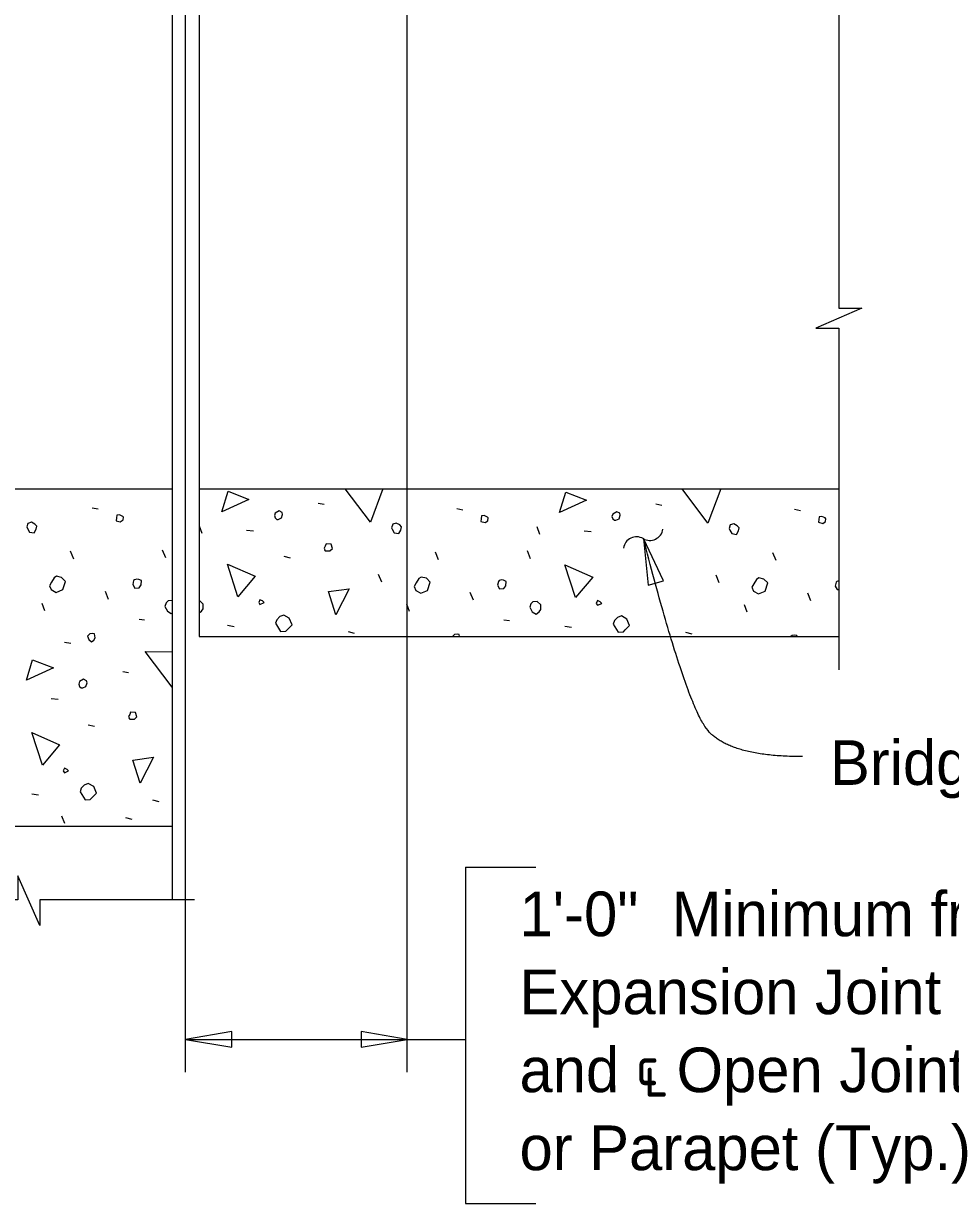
# Model space of a CAD drawing. Extents: x 110341.7 to 110413.5, y 110387.3 to 110417.8.
# Drawn here: x 110363.85 to 110368.03, y 110400.62 to 110405.94 of the extents above; entities that cross this region are included whole.
import ezdxf

# ---------------------------------------------------------------- set-up
doc = ezdxf.new("R2010")
doc.units = 0
for name, color, linetype in [('Border', 7, 'Continuous'), ('CL_Major', 7, 'Continuous'), ('Patterning', 7, 'Continuous'), ('PlotBorder_dp', 7, 'Continuous'), ('SheetBorder_dp', 7, 'Continuous')]:
    doc.layers.add(name, color=color, linetype=linetype)

msp = doc.modelspace()

# ---------------------------------------------------------------- linework, layer by layer
at = {"layer": 'Border'}
for p, q in [((110365.8404, 110402.1361), (110365.8404, 110400.619)), ((110365.8404, 110402.1361), (110366.1585, 110402.1361)), ((110364.5779, 110401.3591), (110365.8404, 110401.3591)), ((110365.8404, 110400.619), (110366.1585, 110400.619))]:
    msp.add_line(p, q, dxfattribs=at)
for points in [[(110367.5259, 110406.5102), (110367.5259, 110404.6594), (110367.6293, 110404.6594), (110367.5259, 110404.6144), (110367.4226, 110404.5694), (110367.5259, 110404.5694), (110367.5259, 110403.0269)], [(110364.6174, 110401.9889), (110363.9204, 110401.9889), (110363.9204, 110401.8726), (110363.821, 110402.0976), (110363.821, 110401.9889), (110363.1658, 110401.9889)]]:
    msp.add_lwpolyline(points, dxfattribs=at)
for points in [[(110366.6439, 110403.6197), (110366.6661, 110403.4097), (110366.7341, 110403.4287)], [(110364.5779, 110401.3591), (110364.7861, 110401.3238), (110364.7861, 110401.3944)], [(110365.5779, 110401.3592), (110365.3696, 110401.3944), (110365.3696, 110401.3239)]]:
    msp.add_lwpolyline(points, close=True, dxfattribs=at)
for centre, start, end in [((110366.6731, 110403.671), 239.8433, 351.5706), ((110366.6132, 110403.5679), 59.8433, 171.5706)]:
    msp.add_arc(centre, 0.0596, start, end, dxfattribs=at)
msp.add_open_spline([(110367.3625, 110402.6354), (110367.0221, 110402.6354), (110366.833, 110402.8909), (110366.6439, 110403.6197)], degree=2, dxfattribs=at)
at = {"layer": 'CL_Major'}
for p, q in [((110365.5778, 110401.2111), (110365.5778, 110414.9771)), ((110364.5779, 110401.2111), (110364.5779, 110406.0949))]:
    msp.add_line(p, q, dxfattribs=at)
at = {"layer": 'Patterning'}
for p, q in [((110364.156, 110403.7587), (110364.1825, 110403.7534)), ((110365.1765, 110403.7799), (110365.203, 110403.7746)), ((110366.7003, 110403.7763), (110366.7268, 110403.771)), ((110365.8023, 110403.7551), (110365.8288, 110403.7498)), ((110367.3261, 110403.7516), (110367.3526, 110403.7463)), ((110364.6532, 110403.642), (110364.6409, 110403.6756)), ((110364.853, 110403.6579), (110364.8848, 110403.6544)), ((110366.1771, 110403.6385), (110366.1647, 110403.6721)), ((110366.3768, 110403.6544), (110366.4086, 110403.6508)), ((110364.0729, 110403.5271), (110364.0587, 110403.5624)), ((110364.4883, 110403.5324), (110364.4742, 110403.5678)), ((110365.7192, 110403.5236), (110365.7051, 110403.5589)), ((110366.1346, 110403.5289), (110366.1205, 110403.5642)), ((110367.243, 110403.52), (110367.2289, 110403.5554)), ((110365.0209, 110403.5395), (110365.0492, 110403.5324)), ((110365.4629, 110403.4228), (110365.4487, 110403.4582)), ((110366.9867, 110403.4193), (110366.9725, 110403.4546)), ((110364.2302, 110403.345), (110364.2161, 110403.3804)), ((110365.8765, 110403.3415), (110365.8624, 110403.3768)), ((110367.4003, 110403.3379), (110367.3862, 110403.3733)), ((110363.9421, 110403.2937), (110363.9297, 110403.3273)), ((110365.5884, 110403.2902), (110365.576, 110403.3238)), ((110367.1122, 110403.2867), (110367.0998, 110403.3203)), ((110364.3681, 110403.2566), (110364.3929, 110403.2531)), ((110364.7664, 110403.2283), (110364.7964, 110403.223)), ((110366.0144, 110403.2531), (110366.0392, 110403.2496)), ((110365.3108, 110403.2001), (110365.3391, 110403.193)), ((110366.2902, 110403.2248), (110366.3202, 110403.2195)), ((110366.8347, 110403.1965), (110366.8629, 110403.1895)), ((110364.0305, 110403.1523), (110364.0605, 110403.147)), ((110364.2939, 110403.0197), (110364.3204, 110403.0144)), ((110363.9704, 110402.8978), (110364.0022, 110402.8942)), ((110364.1383, 110402.7793), (110364.1666, 110402.7723)), ((110363.8837, 110402.4682), (110363.9138, 110402.4629)), ((110364.4282, 110402.4399), (110364.4565, 110402.4328)), ((110364.0322, 110402.3339), (110364.0199, 110402.3674)), ((110364.3062, 110402.3604), (110364.3345, 110402.3533))]:
    msp.add_line(p, q, dxfattribs=at)
for points in [[(110364.7416, 110403.741), (110364.7699, 110403.8329), (110364.8636, 110403.7958), (110364.7416, 110403.741)], [(110365.4116, 110403.6933), (110365.2974, 110403.8435)], [(110365.4678, 110403.8435), (110365.4116, 110403.6933)], [(110366.2654, 110403.7375), (110366.2937, 110403.8294), (110366.3874, 110403.7923), (110366.2654, 110403.7375)], [(110366.9354, 110403.6897), (110366.8185, 110403.8435)], [(110366.9929, 110403.8435), (110366.9354, 110403.6897)], [(110364.2638, 110403.7003), (110364.2832, 110403.695), (110364.2956, 110403.7039), (110364.2974, 110403.7162), (110364.2939, 110403.7198), (110364.2797, 110403.7269), (110364.2673, 110403.7251), (110364.2656, 110403.7127), (110364.2638, 110403.7003)], [(110364.9891, 110403.7056), (110364.9962, 110403.7056), (110365.0103, 110403.7127), (110365.0156, 110403.7286), (110365.0139, 110403.7375), (110364.9997, 110403.7445), (110364.982, 110403.7339), (110364.9785, 110403.7233), (110364.982, 110403.7127), (110364.9891, 110403.7056)], [(110365.9101, 110403.6968), (110365.9296, 110403.6915), (110365.9419, 110403.7003), (110365.9437, 110403.7127), (110365.9402, 110403.7162), (110365.926, 110403.7233), (110365.9137, 110403.7215), (110365.9119, 110403.7092), (110365.9101, 110403.6968)], [(110366.5129, 110403.7021), (110366.52, 110403.7021), (110366.5341, 110403.7092), (110366.5394, 110403.7251), (110366.5377, 110403.7339), (110366.5235, 110403.741), (110366.5059, 110403.7304), (110366.5023, 110403.7198), (110366.5059, 110403.7092), (110366.5129, 110403.7021)], [(110367.4339, 110403.6933), (110367.4534, 110403.688), (110367.4658, 110403.6968), (110367.4675, 110403.7092), (110367.464, 110403.7127), (110367.4498, 110403.7198), (110367.4375, 110403.718), (110367.4357, 110403.7056), (110367.4339, 110403.6933)], [(110363.8643, 110403.665), (110363.8731, 110403.6491), (110363.8943, 110403.6455), (110363.9032, 110403.6614), (110363.9067, 110403.6756), (110363.8979, 110403.6844), (110363.882, 110403.6933), (110363.8661, 110403.688), (110363.8608, 110403.6721), (110363.8643, 110403.665)], [(110365.5106, 110403.6614), (110365.5194, 110403.6455), (110365.5407, 110403.642), (110365.5495, 110403.6579), (110365.553, 110403.6721), (110365.5442, 110403.6809), (110365.5283, 110403.6897), (110365.5124, 110403.6844), (110365.5071, 110403.6685), (110365.5106, 110403.6614)], [(110367.0344, 110403.6579), (110367.0433, 110403.642), (110367.0645, 110403.6385), (110367.0733, 110403.6544), (110367.0768, 110403.6685), (110367.068, 110403.6774), (110367.0521, 110403.6862), (110367.0362, 110403.6809), (110367.0309, 110403.665), (110367.0344, 110403.6579)], [(110365.2083, 110403.5642), (110365.2295, 110403.5642), (110365.2401, 110403.5748), (110365.2348, 110403.5943), (110365.2119, 110403.596), (110365.2083, 110403.5854), (110365.203, 110403.5766), (110365.2083, 110403.5642), (110365.2048, 110403.5678)], [(110364.8141, 110403.3574), (110364.7664, 110403.5041), (110364.8919, 110403.4493), (110364.8141, 110403.3574)], [(110366.3379, 110403.3539), (110366.2902, 110403.5006), (110366.4157, 110403.4458), (110366.3379, 110403.3539)], [(110363.9704, 110403.3892), (110363.9933, 110403.3768), (110364.0234, 110403.3892), (110364.0358, 110403.4263), (110364.0181, 110403.444), (110363.9951, 110403.4493), (110363.9845, 110403.4422), (110363.9721, 110403.4228), (110363.9633, 110403.4069), (110363.9704, 110403.3892)], [(110365.6167, 110403.3857), (110365.6397, 110403.3733), (110365.6697, 110403.3857), (110365.6821, 110403.4228), (110365.6644, 110403.4405), (110365.6414, 110403.4458), (110365.6308, 110403.4387), (110365.6184, 110403.4193), (110365.6096, 110403.4034), (110365.6167, 110403.3857)], [(110367.1405, 110403.3821), (110367.1635, 110403.3698), (110367.1935, 110403.3821), (110367.2059, 110403.4193), (110367.1882, 110403.4369), (110367.1652, 110403.4422), (110367.1546, 110403.4352), (110367.1423, 110403.4157), (110367.1334, 110403.3998), (110367.1405, 110403.3821)], [(110364.3398, 110403.4122), (110364.3487, 110403.3963), (110364.3681, 110403.398), (110364.3769, 110403.4104), (110364.3787, 110403.4299), (110364.3663, 110403.4352), (110364.3575, 110403.4369), (110364.3469, 110403.4334), (110364.3434, 110403.4299), (110364.3398, 110403.4122)], [(110365.256, 110403.2761), (110365.2225, 110403.3804), (110365.3161, 110403.3927), (110365.256, 110403.2761)], [(110365.9861, 110403.4087), (110365.995, 110403.3927), (110366.0144, 110403.3945), (110366.0233, 110403.4069), (110366.025, 110403.4263), (110366.0126, 110403.4316), (110366.0038, 110403.4334), (110365.9932, 110403.4299), (110365.9897, 110403.4263), (110365.9861, 110403.4087)], [(110367.526, 110403.4293), (110367.517, 110403.4263), (110367.5135, 110403.4228), (110367.5099, 110403.4051)], [(110367.5099, 110403.4051), (110367.5188, 110403.3892), (110367.526, 110403.3899)], [(110364.5166, 110403.3396), (110364.4989, 110403.3379), (110364.4901, 110403.3291), (110364.4848, 110403.3132)], [(110364.6391, 110403.284), (110364.6497, 110403.292), (110364.6568, 110403.3026), (110364.6568, 110403.3238), (110364.6409, 110403.3397), (110364.6391, 110403.3396)], [(110364.9131, 110403.322), (110364.9325, 110403.3309), (110364.9255, 110403.3379), (110364.9131, 110403.3432), (110364.9078, 110403.3309), (110364.9131, 110403.322)], [(110366.1311, 110403.3097), (110366.1417, 110403.2884), (110366.1594, 110403.2778), (110366.1735, 110403.2884), (110366.1806, 110403.2991), (110366.1806, 110403.3203), (110366.1647, 110403.3362), (110366.1452, 110403.3344), (110366.1364, 110403.3256), (110366.1311, 110403.3097)], [(110366.4369, 110403.3185), (110366.4564, 110403.3273), (110366.4493, 110403.3344), (110366.4369, 110403.3397), (110366.4316, 110403.3273), (110366.4369, 110403.3185)], [(110364.4848, 110403.3132), (110364.4954, 110403.292), (110364.5131, 110403.2814), (110364.5166, 110403.284)], [(110364.9838, 110403.2372), (110365.0068, 110403.2001), (110365.0298, 110403.2018), (110365.0386, 110403.2107), (110365.0581, 110403.2301), (110365.0457, 110403.2602), (110365.0209, 110403.2743), (110365.0033, 110403.2672), (110364.9891, 110403.2531), (110364.9838, 110403.2372)], [(110366.5076, 110403.2336), (110366.5306, 110403.1965), (110366.5536, 110403.1983), (110366.5624, 110403.2071), (110366.5819, 110403.2266), (110366.5695, 110403.2566), (110366.5447, 110403.2708), (110366.5271, 110403.2637), (110366.5129, 110403.2496), (110366.5076, 110403.2336)], [(110364.1418, 110403.1647), (110364.1524, 110403.1541), (110364.163, 110403.1612), (110364.1701, 110403.1718), (110364.1666, 110403.1895), (110364.1577, 110403.1912), (110364.1454, 110403.1895), (110364.1348, 110403.1788), (110364.1418, 110403.1647)], [(110365.8147, 110403.1769), (110365.8129, 110403.1859), (110365.8041, 110403.1877), (110365.7917, 110403.1859), (110365.7826, 110403.1769)], [(110367.3378, 110403.1769), (110367.3367, 110403.1824), (110367.3279, 110403.1841), (110367.3155, 110403.1824), (110367.31, 110403.1769)], [(110363.859, 110402.9809), (110363.8873, 110403.0728), (110363.981, 110403.0357), (110363.859, 110402.9809)], [(110364.5166, 110402.9494), (110364.3946, 110403.1099), (110364.5166, 110403.1088)], [(110364.1065, 110402.9455), (110364.1135, 110402.9455), (110364.1277, 110402.9526), (110364.133, 110402.9685), (110364.1312, 110402.9773), (110364.1171, 110402.9844), (110364.0994, 110402.9738), (110364.0959, 110402.9632), (110364.0994, 110402.9526), (110364.1065, 110402.9455)], [(110364.3257, 110402.8041), (110364.3469, 110402.8041), (110364.3575, 110402.8147), (110364.3522, 110402.8341), (110364.3292, 110402.8359), (110364.3257, 110402.8253), (110364.3204, 110402.8165), (110364.3257, 110402.8041), (110364.3221, 110402.8076)], [(110363.9315, 110402.5972), (110363.8837, 110402.744), (110364.0092, 110402.6892), (110363.9315, 110402.5972)], [(110364.3734, 110402.5159), (110364.3398, 110402.6202), (110364.4335, 110402.6326), (110364.3734, 110402.5159)], [(110364.0305, 110402.5619), (110364.0499, 110402.5707), (110364.0428, 110402.5778), (110364.0305, 110402.5831), (110364.0252, 110402.5707), (110364.0305, 110402.5619)], [(110364.1012, 110402.477), (110364.1242, 110402.4399), (110364.1471, 110402.4417), (110364.156, 110402.4505), (110364.1754, 110402.47), (110364.163, 110402.5), (110364.1383, 110402.5142), (110364.1206, 110402.5071), (110364.1065, 110402.493), (110364.1012, 110402.477)]]:
    msp.add_lwpolyline(points, dxfattribs=at)
at = {"layer": 'PlotBorder_dp'}
for p, q in [((110364.5166, 110406.0935), (110364.5166, 110401.9888)), ((110364.6391, 110406.0935), (110364.6391, 110403.1769)), ((110357.2147, 110403.8435), (110364.5166, 110403.8435)), ((110364.6391, 110403.8435), (110367.526, 110403.8435)), ((110364.6391, 110403.1769), (110367.526, 110403.1769)), ((110363.2966, 110402.3212), (110364.5166, 110402.3212))]:
    msp.add_line(p, q, dxfattribs=at)

# ---------------------------------------------------------------- texts
at = {"layer": 'SheetBorder_dp'}
for s, p in [('Bridge Deck', (110367.4861, 110402.5077)), ('1\'-0"  Minimum from ℄ ', (110366.085, 110401.825)), ('Expansion Joint (shown)', (110366.085, 110401.473)), ('and ℄ Open Joint in Barrier ', (110366.085, 110401.121)), ('or Parapet (Typ.)', (110366.085, 110400.769))]:
    msp.add_text(s, height=0.2016, dxfattribs=at).set_placement(p)

doc.saveas('drawing.dxf')
